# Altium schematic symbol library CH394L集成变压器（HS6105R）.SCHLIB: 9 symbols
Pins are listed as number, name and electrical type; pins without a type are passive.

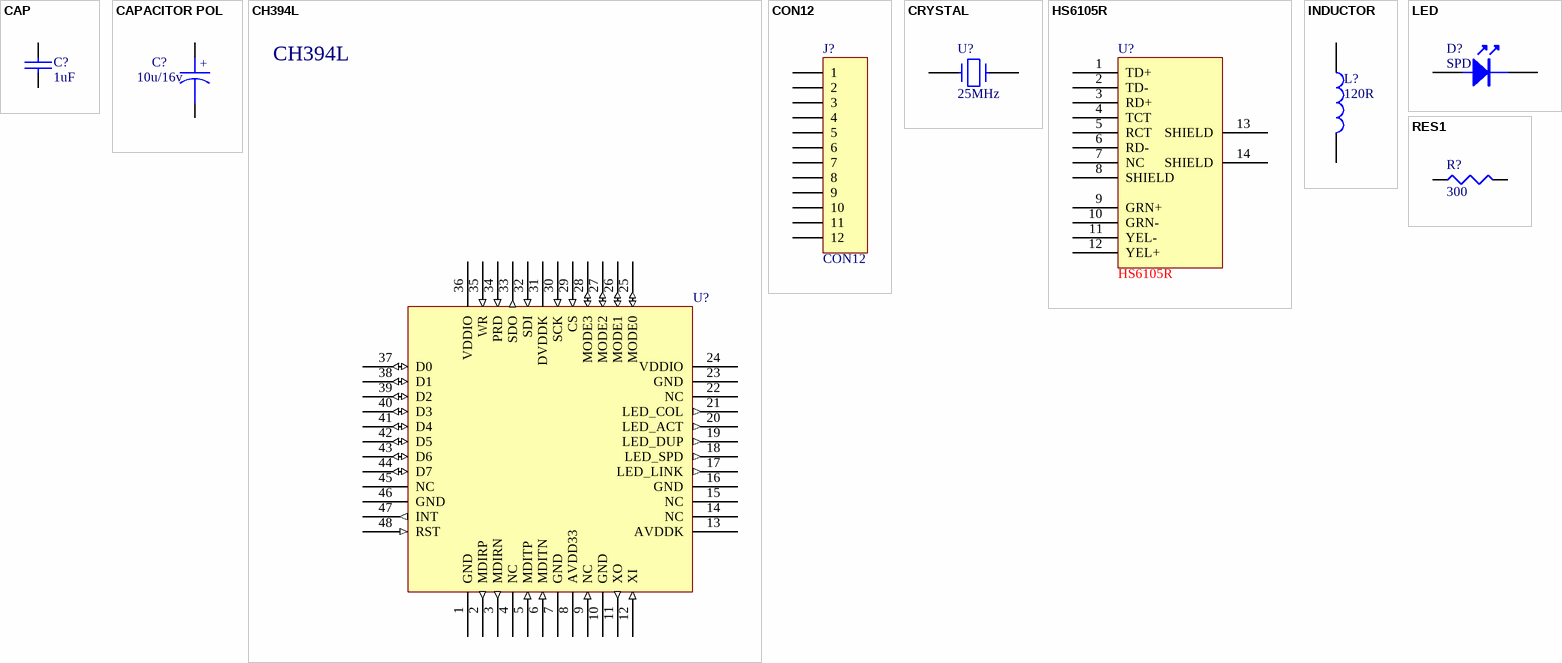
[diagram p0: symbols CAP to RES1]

## CAP
designator C?, comment 1uF
Capacitor
footprint 0603
pins: 1, 2

## CAPACITOR POL
designator C?, comment 10u/16v
Capacitor
footprint 3216
pins: 1, 2

## CH394L
designator U?
footprint LQFP48-W5500/W5100S/W6100/C8T6
pins: 1 GND (power), 2 MDIRP (out), 3 MDIRN (out), 4 NC (power), 5 MDITP (in), 6 MDITN (in), 7 GND (power), 8 AVDD33 (power), 9 NC (in), 10 GND (power), 11 XO (out), 12 XI (in), 13 AVDDK (power), 14 NC (power), 15 NC (power), 16 GND (power), 17 LED_LINK (out), 18 LED_SPD (out), 19 LED_DUP (out), 20 LED_ACT (out), 21 LED_COL (out), 22 NC (power), 23 GND (power), 24 VDDIO (power), 25 MODE0 (io), 26 MODE1 (io), 27 MODE2 (io), 28 MODE3 (io), 29 CS (in), 30 SCK (in), 31 DVDDK (power), 32 SDI (in), 33 SDO (out), 34 PRD (in), 35 WR (in), 36 VDDIO (power), 37 D0 (io), 38 D1 (io), 39 D2 (io), 40 D3 (io), 41 D4 (io), 42 D5 (io), 43 D6 (io), 44 D7 (io), 45 NC (power), 46 GND (power), 47 INT (out), 48 RST (in)

## CON12
designator J?
Connector
footprint SIP12
pins: 1, 2, 3, 4, 5, 6, 7, 8, 9, 10, 11, 12

## CRYSTAL
designator U?, comment 25MHz
Crystal
footprint XTAL-49S
pins: 1, 2

## HS6105R
designator U?
footprint RJ45-HS6105R
pins: 1 TD+, 2 TD-, 3 RD+, 4 TCT, 5 RCT, 6 RD-, 7 NC, 8 SHIELD, 9 GRN+, 10 GRN-, 11 YEL-, 12 YEL+, 13 SHIELD, 14 SHIELD

## INDUCTOR
designator L?, comment 120R
footprint 0603
pins: 1, 2

## LED
designator D?, comment SPD
pins: A 1, K 2

## RES1
designator R?, comment 300
footprint 0603
pins: 1, 2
